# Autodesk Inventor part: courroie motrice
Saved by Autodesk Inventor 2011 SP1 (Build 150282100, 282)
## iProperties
Created: 2010-12
Part Number: courroie motrice
Document SubType Name: Modeling
Designer: eric
Density: 1 g/cm^3
Author: eric
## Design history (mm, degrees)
feature "Base1"
node "Solide1"
node "Corps solides"
node "Corps surfaciques"
